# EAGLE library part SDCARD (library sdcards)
SD Card Holder
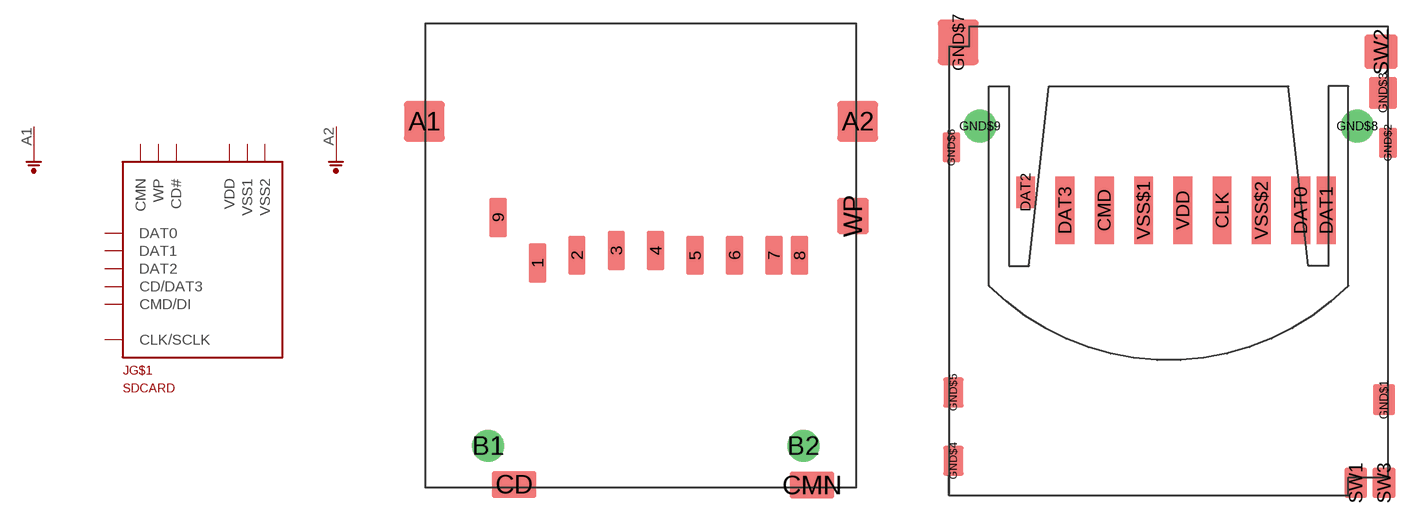
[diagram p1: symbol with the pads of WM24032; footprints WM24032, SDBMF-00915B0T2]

Designator prefix J; gates G$1=SCDARD G$2=GND G$3=GND

## SDCARDDIGIKEY  [WM24032]
1  G$1:CD/DAT3
2  G$1:CMD/DI
3  G$1:VSS1  pwr
4  G$1:VDD  pwr
5  G$1:CLK/SCLK
6  G$1:VSS2  pwr
7  G$1:DAT0
8  G$1:DAT1
9  G$1:DAT2
A1  G$2:GND  pwr
A2  G$3:GND  pwr
CD  G$1:CD#  out
CMN  G$1:CMN  in
WP  G$1:WP  out

## SDCARDNEWARK  [SDBMF-00915B0T2]
CLK  G$1:CLK/SCLK
CMD  G$1:CMD/DI
DAT0  G$1:DAT0
DAT1  G$1:DAT1
DAT2  G$1:DAT2
DAT3  G$1:CD/DAT3
GND$1  G$2:GND  pwr
GND$5  G$3:GND  pwr
SW1  G$1:CD#  out
SW2  G$1:WP  out
SW3  G$1:CMN  in
VDD  G$1:VDD  pwr
VSS$1  G$1:VSS1  pwr
VSS$2  G$1:VSS2  pwr

## SDCARDMOUSER  [SCDA1A]
1  G$1:CD/DAT3
2  G$1:CMD/DI
3  G$1:VSS1  pwr
4  G$1:VDD  pwr
5  G$1:CLK/SCLK
6  G$1:VSS2  pwr
7  G$1:DAT0
8  G$1:DAT1
9  G$1:DAT2
10  G$1:CD#  out
11  G$1:CMN  in
12  G$1:WP  out
13  G$2:GND  pwr
14  G$3:GND  pwr

## SDCARDUNKNOWN  [SDCMF-10915W010]
1  G$1:CD/DAT3
2  G$1:CMD/DI
3  G$1:VSS1  pwr
4  G$1:VDD  pwr
5  G$1:CLK/SCLK
6  G$1:VSS2  pwr
7  G$1:DAT0
8  G$1:DAT1
9  G$1:DAT2
10  G$1:WP  out
11  G$1:CD#  out
14  G$2:GND  pwr
15  G$1:CMN  in
16  G$3:GND  pwr

## Footprint WM24032 (pad centres in mm)
500998-0900 (Digikey)
smd 1.1 x 2.5: 1 -6.975,-2.9; 2 -4.475,-2.4; 3 -1.975,-2.1; 4 0.525,-2.1; 5 3.025,-2.4; 6 5.525,-2.4; 7 8.025,-2.4; 8 9.65,-2.4; 9 -9.475,0
smd 2.6 x 2.6: A1 -14.15,6.1; A2 13.35,6.1
drill 1.36 pad 1.46 round: B1 -10.1,-14.5; B2 9.9,-14.5
smd 2.8 x 1.7: CD -8.45,-16.95; CMN 10.45,-17
smd 2 x 2.3: WP 13.05,0.1

## Footprint SDBMF-00915B0T2 (pad centres in mm)
SDBMF-00915B0T2 (Farnell, Newark)
smd 1.2 x 4.3: CLK 3.1,-1.14; CMD -4.4,-1.14; DAT0 8.1,-1.14; DAT1 9.725,-1.14; DAT3 -6.9,-1.14; VDD 0.6,-1.14; VSS$1 -1.9,-1.14; VSS$2 5.6,-1.14
smd 1.2 x 2: DAT2 -9.4,0.01
smd 1.4 x 1.95: GND$1 13.4,-13.2; SW1 11.6,-18.5
smd 1.143 x 1.905: GND$2 13.654,3.15; GND$6 -14.127,2.85
smd 1.778 x 2.032: GND$3 13.327,6.327
smd 1.3 x 1.9: GND$4 -14,-17.1; GND$5 -14,-12.75
smd 2.6 x 2.9: GND$7 -13.7,9.55
drill 1.4 pad 1.5 round: GND$8 11.7,4.2; GND$9 -12.3,4.2
smd 2.1 x 2.2: SW2 13.2,8.95
smd 1.45 x 1.95: SW3 13.4,-18.5

## Footprint SCDA1A (pad centres in mm)
SCDA1A0900, SCDA1A0901, SCDA1A0801, SCDA1A1301, SCDA1A1401, SCDA1A1501 (Mouser)
smd 1 x 2.95: 1 -7.5,-10.125; 2 -5,-10.125; 3 -2.5,-10.125; 4 0,-10.125; 5 2.5,-10.125; 6 5,-10.125; 7 7.5,-10.125; 8 10,-10.125; 9 -10,-10.125; 10 12.5,-10.125; 13 -12.5,-10.125
smd 1.7 x 1.8: 11 13.85,-4.65
smd 1.7 x 2.9: 12 13.85,16.65
smd 1.9 x 1.8: 14 -13.85,17
hole 1.05 at -12.1,-5.9
hole 1.5 at 12.1,-5.9
hole 1.4 at 12.1,14.2
hole 1.4 at -12.1,14.2

## Footprint SDCMF-10915W010 (pad centres in mm)
SD card connector KINGFONT SDCMF-10915W010
smd 0.711 x 1.422: 1 7.366,13.462; 2 4.826,13.462; 3 2.286,13.462; 4 -0.254,13.462; 5 -2.794,13.462; 6 -5.334,13.462; 7 -7.874,13.462; 8 -9.398,13.462; 9 9.906,13.462; 10 -11.938,13.462; 11 -10.668,13.462
smd 1.27 x 2.54: 12 12.192,11.43; 13 13.97,-10.16; 14 -13.208,-10.16; 15 -13.208,11.43; 16 -13.208,-2.54; 17 13.97,-2.54
hole 1.6 at 9.906,10.414
hole 1.1 at -11.176,10.414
